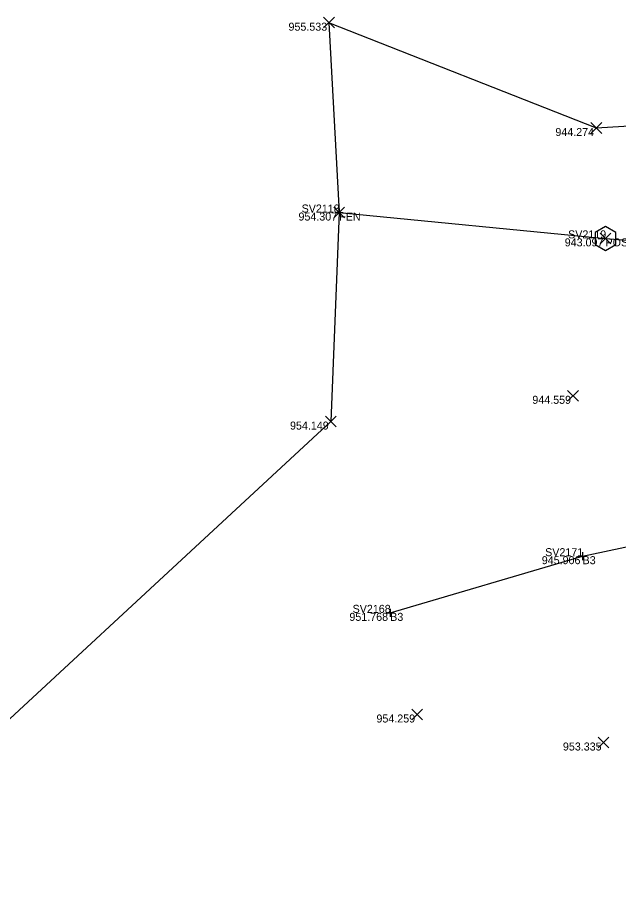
# Model space of a CAD drawing. Extents: x 2065431 to 2068157, y 709104 to 709719.
# Drawn here: x 2066286.8 to 2066361.9, y 709593.7 to 709701.9 of the extents above; entities that cross this region are included whole.
import ezdxf

# ---------------------------------------------------------------- set-up
doc = ezdxf.new("R2010")
doc.units = 0
for name, color, linetype in [('DT_X_Terrain_Boundary', 7, 'Continuous'), ('RD_X_Fence', 7, 'Continuous'), ('RS_Raster1', 7, 'Continuous'), ('RW_X_CL_100_Bearings', 7, 'Continuous'), ('RW_X_CL_100_Distances', 7, 'Continuous'), ('SV_X_Break_Lines', 7, 'Continuous'), ('SV_X_Mon_Cells_Found', 7, 'Continuous'), ('SV_X_Text_Elevation', 7, 'Continuous'), ('SV_X_Text_Name', 7, 'Continuous')]:
    doc.layers.add(name, color=color, linetype=linetype)

msp = doc.modelspace()

# ---------------------------------------------------------------- linework, layer by layer
at = {"layer": 'DT_X_Terrain_Boundary'}
msp.add_lwpolyline([(2066649.44, 709584.58), (2066543.44, 709596.37), (2066510.56, 709629.51), (2066507.17, 709644.46), (2066473.93, 709666.44), (2066463.59, 709680.71), (2066437.89, 709682.56), (2066422.56, 709690.18), (2066414.56, 709691.38), (2066359.14, 709688.04), (2066325.73, 709701.2), (2066327.01, 709677.48), (2066325.95, 709651.36), (2066268.91, 709598.56), (2066231.54, 709603.08), (2066151.93, 709594.95), (2066146.99, 709595.72), (2066142.05, 709596.5), (2066137.11, 709597.27), (2066132.17, 709598.05)], dxfattribs=at)
at = {"layer": 'RD_X_Fence'}
msp.add_lwpolyline([(2066327.01, 709677.48), (2066360.29, 709674.25), (2066368.48, 709673.58)], dxfattribs=at)
at = {"layer": 'RS_Raster1'}
for p, q in [((2066326.51, 709677.48), (2066327.51, 709677.48)), ((2066327.01, 709677.98), (2066327.01, 709676.98)), ((2066327.01, 709677.48), (2066327.01, 709677.48)), ((2066357.42, 709635.04), (2066357.42, 709634.04)), ((2066356.92, 709634.54), (2066357.92, 709634.54)), ((2066357.42, 709634.54), (2066357.42, 709634.54)), ((2066332.88, 709627.46), (2066333.88, 709627.46)), ((2066333.38, 709627.96), (2066333.38, 709626.96)), ((2066333.38, 709627.46), (2066333.38, 709627.46))]:
    msp.add_line(p, q, dxfattribs=at)
at = {"layer": 'RW_X_CL_100_Bearings'}
for p, q in [((2066325.06, 709700.54), (2066326.4, 709701.87)), ((2066325.06, 709701.87), (2066326.4, 709700.54)), ((2066358.47, 709687.37), (2066359.81, 709688.71)), ((2066358.47, 709688.71), (2066359.81, 709687.37)), ((2066326.35, 709676.82), (2066327.68, 709678.15)), ((2066326.35, 709678.15), (2066327.68, 709676.82)), ((2066359.62, 709673.58), (2066360.96, 709674.91)), ((2066359.62, 709674.91), (2066360.96, 709673.58)), ((2066355.55, 709653.92), (2066356.89, 709655.25)), ((2066355.55, 709655.25), (2066356.89, 709653.92)), ((2066325.28, 709650.69), (2066326.61, 709652.03)), ((2066325.28, 709652.03), (2066326.61, 709650.69)), ((2066336.08, 709614.09), (2066337.41, 709615.43)), ((2066336.08, 709615.43), (2066337.41, 709614.09)), ((2066359.37, 709610.59), (2066360.7, 709611.93)), ((2066359.37, 709611.93), (2066360.7, 709610.59))]:
    msp.add_line(p, q, dxfattribs=at)
at = {"layer": 'RW_X_CL_100_Distances'}
msp.add_lwpolyline([(2066358.99, 709673.5), (2066360.29, 709672.75), (2066361.59, 709673.5), (2066361.59, 709675), (2066360.29, 709675.75), (2066358.99, 709675), (2066358.99, 709673.5)], dxfattribs=at)
at = {"layer": 'SV_X_Break_Lines'}
msp.add_lwpolyline([(2066333.38, 709627.46), (2066357.42, 709634.54), (2066378.4, 709638.99), (2066384.87, 709638.51)], dxfattribs=at)

# ---------------------------------------------------------------- texts
at = {"layer": 'SV_X_Mon_Cells_Found'}
for s, p in [('SV2118', (2066322.31, 709677.48)), ('SV2119', (2066355.61, 709674.25)), ('SV2171', (2066352.74, 709634.54)), ('SV2168', (2066328.68, 709627.46))]:
    msp.add_text(s, height=1, dxfattribs=at).set_placement(p)
at = {"layer": 'SV_X_Text_Elevation'}
for s, p in [('FEN', (2066327.01, 709676.48)), ('POST', (2066360.29, 709673.25)), ('B3', (2066357.42, 709633.54)), ('B3', (2066333.38, 709626.46))]:
    msp.add_text(s, height=1, dxfattribs=at).set_placement(p)
at = {"layer": 'SV_X_Text_Name'}
for s, p in [('955.533', (2066320.67, 709700.2)), ('944.274', (2066354.02, 709687.04)), ('954.307', (2066321.92, 709676.48)), ('954.307', (2066321.92, 709676.48)), ('943.097', (2066355.19, 709673.25)), ('943.097', (2066355.19, 709673.25)), ('944.559', (2066351.14, 709653.58)), ('954.149', (2066320.86, 709650.36)), ('945.906', (2066352.32, 709633.54)), ('951.768', (2066328.28, 709626.46)), ('954.259', (2066331.66, 709613.76)), ('953.335', (2066354.96, 709610.26))]:
    msp.add_text(s, height=1, dxfattribs=at).set_placement(p)

doc.saveas('drawing.dxf')
